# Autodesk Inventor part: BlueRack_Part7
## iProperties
Shininess: 64.0
Length Units: 11272
Angle Units: 11279
Time Units: 11290
Mass Units: 11286
Length Display Precision: 3
Angle Display Precision: 2
Compacted: True
Part Number: BlueRack_Part7
Document SubType Name: Modeling
Created: 2004-12
Designer: John Blackburn
Manufacturer: Standard
Standards Organization: Custom
Material: Steel, Mild
Density: 0.0
Volumn: 0.0
Area: 0.0
PropertySet Name: Model Information
Control State: 0
Master: False
Checked Out: False
Author: John Blackburn
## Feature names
1. Extrusion1
